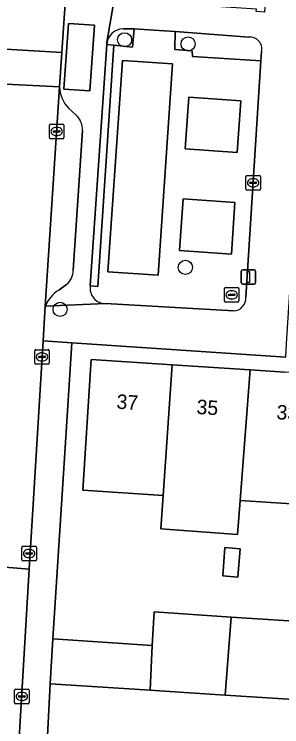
# Model space of a CAD drawing. Extents: x 160349 to 161355, y 381727 to 382854.
# Drawn here: x 160526.67 to 160545.13, y 382016.9 to 382066.09 of the extents above; entities that cross this region are included whole.
import ezdxf

# ---------------------------------------------------------------- set-up
doc = ezdxf.new("R2010")
doc.units = 0
for name, color, linetype in [('IMGEO_Boom', 7, 'Continuous'), ('IMGEO_Erf', 7, 'Continuous'), ('IMGEO_Groenvoorziening', 7, 'Continuous'), ('IMGEO_Haag', 7, 'Continuous'), ('IMGEO_Kolk', 7, 'Continuous'), ('IMGEO_Lichtmast', 7, 'Continuous'), ('IMGEO_Muur', 7, 'Continuous'), ('IMGEO_Pand', 7, 'Continuous'), ('IMGEO_Pand_nummerreeks', 7, 'Continuous'), ('IMGEO_Parkeervlak_open', 7, 'Continuous'), ('IMGEO_Rijbaan_lokaal_open', 7, 'Continuous'), ('IMGEO_Rioolput', 7, 'Continuous'), ('IMGEO_Terreindeel_open', 7, 'Continuous'), ('IMGEO_Voetpad_open', 7, 'Continuous')]:
    doc.layers.add(name, color=color, linetype=linetype)

msp = doc.modelspace()

# ---------------------------------------------------------------- linework, layer by layer
at = {"layer": 'IMGEO_Boom'}
for centre in [(160534.279, 382064.333), (160538.67, 382064.045), (160538.48, 382048.617), (160529.832, 382045.718)]:
    msp.add_circle(centre, 0.489, dxfattribs=at)
at = {"layer": 'IMGEO_Erf'}
for points in [[(160545.411, 382042.407), (160530.648, 382043.401), (160530.156, 382035.8), (160529.324, 382022.967), (160536.182, 382022.498), (160536.333, 382024.823), (160541.648, 382024.475), (160547.428, 382024.097)], [(160545.801, 382032.284), (160542.262, 382032.515), (160542.083, 382030.166), (160536.776, 382030.571), (160536.951, 382032.863), (160531.398, 382033.226), (160531.983, 382042.262), (160537.561, 382041.895), (160542.951, 382041.54), (160545.344, 382041.383)]]:
    msp.add_lwpolyline(points, dxfattribs=at)
msp.add_lwpolyline([(160541.057, 382027.312), (160541.206, 382029.27), (160542.259, 382029.19), (160542.11, 382027.231)], close=True, dxfattribs=at)
at = {"layer": 'IMGEO_Groenvoorziening'}
for points in [[(160533.05, 382064.002), (160533.532, 382063.953), (160534.836, 382063.824), (160534.948, 382065.084), (160534.185, 382065.082)], [(160542.854, 382064.514), (160537.786, 382064.905), (160537.741, 382063.667), (160538.946, 382063.573), (160538.961, 382063.186), (160543.699, 382062.877), (160543.741, 382063.523)]]:
    msp.add_lwpolyline(points, dxfattribs=at)
for points in [[(160531.913, 382047.338), (160532.438, 382047.299), (160533.532, 382063.953), (160533.05, 382064.002)], [(160536.594, 382048.071), (160537.601, 382062.665), (160534.129, 382062.904), (160533.122, 382048.311)]]:
    msp.add_lwpolyline(points, close=True, dxfattribs=at)
for centre, radius, start, end in [((160534.205, 382063.924), 1.158, 91.0047, 176.1505), ((160542.94, 382063.698), 0.82, 347.6775, 95.9832)]:
    msp.add_arc(centre, radius, start, end, dxfattribs=at)
at = {"layer": 'IMGEO_Haag'}
msp.add_lwpolyline([(160531.913, 382047.338), (160532.438, 382047.299), (160533.532, 382063.953), (160533.05, 382064.002)], close=True, dxfattribs=at)
at = {"layer": 'IMGEO_Kolk'}
for p, q in [((160529.094, 382057.573), (160529.094, 382058.425)), ((160529.169, 382058.499), (160530.021, 382058.499)), ((160530.095, 382058.425), (160530.095, 382057.573)), ((160529.353, 382057.993), (160529.353, 382058.005)), ((160529.791, 382057.956), (160529.393, 382057.956)), ((160529.396, 382058.042), (160529.794, 382058.042)), ((160529.582, 382058.279), (160529.607, 382058.279)), ((160529.837, 382058.005), (160529.837, 382057.993)), ((160530.021, 382057.499), (160529.169, 382057.499)), ((160529.605, 382057.719), (160529.58, 382057.719)), ((160542.658, 382054.03), (160542.658, 382054.882)), ((160542.733, 382054.956), (160543.585, 382054.956)), ((160543.659, 382054.882), (160543.659, 382054.03)), ((160542.917, 382054.45), (160542.917, 382054.462)), ((160543.355, 382054.413), (160542.957, 382054.413)), ((160542.96, 382054.499), (160543.358, 382054.499)), ((160543.146, 382054.736), (160543.171, 382054.736)), ((160543.401, 382054.462), (160543.401, 382054.45)), ((160543.585, 382053.956), (160542.733, 382053.956)), ((160543.169, 382054.176), (160543.144, 382054.176)), ((160528.08, 382042.008), (160528.08, 382042.86)), ((160528.155, 382042.934), (160529.007, 382042.934)), ((160528.568, 382042.714), (160528.593, 382042.714)), ((160529.081, 382042.86), (160529.081, 382042.008)), ((160528.339, 382042.428), (160528.339, 382042.44)), ((160528.777, 382042.391), (160528.379, 382042.391)), ((160528.382, 382042.477), (160528.78, 382042.477)), ((160528.591, 382042.154), (160528.566, 382042.154)), ((160528.823, 382042.44), (160528.823, 382042.428)), ((160529.007, 382041.934), (160528.155, 382041.934)), ((160527.269, 382029.359), (160528.121, 382029.359)), ((160527.194, 382028.433), (160527.194, 382029.285)), ((160527.453, 382028.853), (160527.453, 382028.865)), ((160527.891, 382028.816), (160527.493, 382028.816)), ((160527.496, 382028.902), (160527.894, 382028.902)), ((160527.682, 382029.139), (160527.707, 382029.139)), ((160527.937, 382028.865), (160527.937, 382028.853)), ((160528.195, 382029.285), (160528.195, 382028.433)), ((160528.121, 382028.359), (160527.269, 382028.359)), ((160527.705, 382028.579), (160527.68, 382028.579)), ((160526.763, 382019.491), (160527.615, 382019.491)), ((160526.688, 382018.565), (160526.688, 382019.417)), ((160526.947, 382018.985), (160526.947, 382018.997)), ((160526.99, 382019.034), (160527.388, 382019.034)), ((160527.176, 382019.271), (160527.201, 382019.271)), ((160527.431, 382018.997), (160527.431, 382018.985)), ((160527.689, 382019.417), (160527.689, 382018.565)), ((160527.615, 382018.491), (160526.763, 382018.491)), ((160527.385, 382018.948), (160526.987, 382018.948)), ((160527.199, 382018.711), (160527.174, 382018.711))]:
    msp.add_line(p, q, dxfattribs=at)
for points in [[(160529.094, 382057.573), (160529.094, 382058.425)], [(160529.169, 382058.499), (160530.021, 382058.499)], [(160530.095, 382058.425), (160530.095, 382057.573)], [(160530.021, 382057.499), (160529.169, 382057.499)], [(160542.658, 382054.03), (160542.658, 382054.882)], [(160542.733, 382054.956), (160543.585, 382054.956)], [(160543.659, 382054.882), (160543.659, 382054.03)], [(160543.585, 382053.956), (160542.733, 382053.956)], [(160528.08, 382042.008), (160528.08, 382042.86)], [(160528.155, 382042.934), (160529.007, 382042.934)], [(160529.081, 382042.86), (160529.081, 382042.008)], [(160529.007, 382041.934), (160528.155, 382041.934)], [(160527.269, 382029.359), (160528.121, 382029.359)], [(160527.194, 382028.433), (160527.194, 382029.285)], [(160528.195, 382029.285), (160528.195, 382028.433)], [(160528.121, 382028.359), (160527.269, 382028.359)], [(160526.763, 382019.491), (160527.615, 382019.491)], [(160526.688, 382018.565), (160526.688, 382019.417)], [(160527.689, 382019.417), (160527.689, 382018.565)], [(160527.615, 382018.491), (160526.763, 382018.491)]]:
    msp.add_lwpolyline(points, dxfattribs=at)
for centre, radius, start, end in [((160529.171, 382058.423), 0.0765, 91.552, 178.448), ((160529.171, 382058.423), 0.0765, 91.552, 178.448), ((160530.019, 382058.423), 0.0765, 1.552, 88.448), ((160530.019, 382058.423), 0.0765, 1.552, 88.448), ((160529.393, 382058.002), 0.0403, 85.8775, 175.7526), ((160529.39, 382057.992), 0.0366, 178.938, 274.7102), ((160529.794, 382057.999), 0.043, 264.8664, 352.4533), ((160529.798, 382058.004), 0.0386, 1.7309, 96.639), ((160529.171, 382057.575), 0.0765, 181.552, 268.448), ((160529.171, 382057.575), 0.0765, 181.552, 268.448), ((160530.019, 382057.575), 0.0765, 271.552, 358.448), ((160530.019, 382057.575), 0.0765, 271.552, 358.448), ((160542.735, 382054.88), 0.0765, 91.552, 178.448), ((160542.735, 382054.88), 0.0765, 91.552, 178.448), ((160543.583, 382054.88), 0.0765, 1.552, 88.448), ((160543.583, 382054.88), 0.0765, 1.552, 88.448), ((160542.957, 382054.459), 0.0403, 85.8775, 175.7526), ((160542.954, 382054.449), 0.0366, 178.938, 274.7102), ((160543.358, 382054.456), 0.043, 264.8664, 352.4533), ((160543.362, 382054.461), 0.0386, 1.7309, 96.639), ((160542.735, 382054.032), 0.0765, 181.552, 268.448), ((160542.735, 382054.032), 0.0765, 181.552, 268.448), ((160543.583, 382054.032), 0.0765, 271.552, 358.448), ((160543.583, 382054.032), 0.0765, 271.552, 358.448), ((160528.157, 382042.858), 0.0765, 91.552, 178.448), ((160528.157, 382042.858), 0.0765, 91.552, 178.448), ((160529.005, 382042.858), 0.0765, 1.552, 88.448), ((160529.005, 382042.858), 0.0765, 1.552, 88.448), ((160528.379, 382042.437), 0.0403, 85.8775, 175.7526), ((160528.376, 382042.427), 0.0366, 178.938, 274.7102), ((160528.78, 382042.434), 0.043, 264.8664, 352.4533), ((160528.784, 382042.439), 0.0386, 1.7309, 96.639), ((160528.157, 382042.01), 0.0765, 181.552, 268.448), ((160528.157, 382042.01), 0.0765, 181.552, 268.448), ((160529.005, 382042.01), 0.0765, 271.552, 358.448), ((160529.005, 382042.01), 0.0765, 271.552, 358.448), ((160527.271, 382029.283), 0.0765, 91.552, 178.448), ((160527.271, 382029.283), 0.0765, 91.552, 178.448), ((160528.119, 382029.283), 0.0765, 1.552, 88.448), ((160528.119, 382029.283), 0.0765, 1.552, 88.448), ((160527.493, 382028.862), 0.0403, 85.8775, 175.7526), ((160527.49, 382028.852), 0.0366, 178.938, 274.7102), ((160527.894, 382028.859), 0.043, 264.8664, 352.4533), ((160527.898, 382028.864), 0.0386, 1.7309, 96.639), ((160527.271, 382028.435), 0.0765, 181.552, 268.448), ((160527.271, 382028.435), 0.0765, 181.552, 268.448), ((160528.119, 382028.435), 0.0765, 271.552, 358.448), ((160528.119, 382028.435), 0.0765, 271.552, 358.448), ((160526.765, 382019.415), 0.0765, 91.552, 178.448), ((160526.765, 382019.415), 0.0765, 91.552, 178.448), ((160527.613, 382019.415), 0.0765, 1.552, 88.448), ((160527.613, 382019.415), 0.0765, 1.552, 88.448), ((160526.987, 382018.994), 0.0403, 85.8775, 175.7526), ((160526.984, 382018.984), 0.0366, 178.938, 274.7102), ((160527.388, 382018.991), 0.043, 264.8664, 352.4533), ((160527.392, 382018.996), 0.0386, 1.7309, 96.639), ((160526.765, 382018.567), 0.0765, 181.552, 268.448), ((160526.765, 382018.567), 0.0765, 181.552, 268.448), ((160527.613, 382018.567), 0.0765, 271.552, 358.448), ((160527.613, 382018.567), 0.0765, 271.552, 358.448)]:
    msp.add_arc(centre, radius, start, end, dxfattribs=at)
for centre, major_axis, ratio, start_param, end_param in [((160529.581, 382057.999), (-0.387, 0.002), 0.722429, 4.712389, 7.853982), ((160529.606, 382057.999), (-0.39, 0.002), 0.717154, 1.570796, 4.712389), ((160543.145, 382054.456), (-0.387, 0.002), 0.722429, 4.712389, 7.853982), ((160543.17, 382054.456), (-0.39, 0.002), 0.717154, 1.570796, 4.712389), ((160528.567, 382042.434), (-0.387, 0.002), 0.722429, 4.712389, 7.853982), ((160528.592, 382042.434), (-0.39, 0.002), 0.717154, 1.570796, 4.712389), ((160527.681, 382028.859), (-0.387, 0.002), 0.722429, 4.712389, 7.853982), ((160527.706, 382028.859), (-0.39, 0.002), 0.717154, 1.570796, 4.712389), ((160527.175, 382018.991), (-0.387, 0.002), 0.722429, 4.712389, 7.853982), ((160527.2, 382018.991), (-0.39, 0.002), 0.717154, 1.570796, 4.712389)]:
    msp.add_ellipse(centre, major_axis=major_axis, ratio=ratio, start_param=start_param, end_param=end_param, dxfattribs=at)
at = {"layer": 'IMGEO_Lichtmast'}
for p, q in [((160542.337, 382047.555), (160542.337, 382048.355)), ((160542.337, 382048.355), (160542.337, 382047.555)), ((160542.437, 382048.455), (160543.227, 382048.455)), ((160543.227, 382048.455), (160542.437, 382048.455)), ((160543.327, 382048.355), (160543.327, 382047.555)), ((160543.327, 382047.555), (160543.327, 382048.355)), ((160543.227, 382047.455), (160542.437, 382047.455)), ((160542.437, 382047.455), (160543.227, 382047.455))]:
    msp.add_line(p, q, dxfattribs=at)
msp.add_lwpolyline([(160542.757, 382048.33), (160542.907, 382048.33), (160542.907, 382047.58), (160542.757, 382047.58), (160542.757, 382048.33)], dxfattribs=at)
for centre, start, end in [((160542.437, 382048.355), 90, 180), ((160542.437, 382048.355), 90, 180), ((160543.227, 382048.355), 0, 90), ((160543.227, 382048.355), 360, 90), ((160542.437, 382047.555), 180, 270), ((160542.437, 382047.555), 180, 270), ((160543.227, 382047.555), 270, 0), ((160543.227, 382047.555), 270, 0)]:
    msp.add_arc(centre, 0.1, start, end, dxfattribs=at)
at = {"layer": 'IMGEO_Muur'}
msp.add_lwpolyline([(160530.156, 382035.8), (160529.324, 382022.967)], dxfattribs=at)
at = {"layer": 'IMGEO_Pand'}
for points in [[(160537.561, 382041.895), (160531.983, 382042.262), (160531.398, 382033.226), (160536.951, 382032.863)], [(160542.262, 382032.515), (160542.951, 382041.54), (160537.561, 382041.895), (160536.951, 382032.863), (160536.776, 382030.571), (160542.083, 382030.166)], [(160548.248, 382036.577), (160548.55, 382041.172), (160545.344, 382041.383), (160542.951, 382041.54), (160542.262, 382032.515), (160545.801, 382032.284), (160545.703, 382030.787), (160547.858, 382030.645), (160548.136, 382034.873)], [(160541.057, 382027.312), (160542.11, 382027.231), (160542.259, 382029.19), (160541.206, 382029.27)], [(160536.043, 382019.426), (160538.419, 382019.273), (160541.237, 382019.089), (160541.648, 382024.475), (160536.333, 382024.823), (160536.182, 382022.498)], [(160548.812, 382023.329), (160548.856, 382024.004), (160547.428, 382024.097), (160541.648, 382024.475), (160541.237, 382019.089), (160548.504, 382018.615), (160548.514, 382018.767)], [(160536.043, 382019.426), (160536.182, 382022.498), (160529.324, 382022.967), (160529.135, 382019.87)]]:
    msp.add_lwpolyline(points, close=True, dxfattribs=at)
at = {"layer": 'IMGEO_Parkeervlak_open'}
msp.add_lwpolyline([(160531.893, 382060.81), (160532.199, 382065.34), (160530.403, 382065.462), (160530.097, 382060.932)], close=True, dxfattribs=at)
for points in [[(160529.795, 382061.08), (160528.807, 382045.931)], [(160530.934, 382059.136), (160530.426, 382059.593)], [(160530.741, 382048.431), (160531.366, 382058.069)], [(160529.737, 382047.047), (160530.283, 382047.428)]]:
    msp.add_lwpolyline(points, dxfattribs=at)
for centre, radius, start, end in [((160531.964, 382061.123), 2.169, 181.1318, 224.8555), ((160530.053, 382058.159), 1.316, 356.0973, 47.9862), ((160529.365, 382048.453), 1.376, 311.8434, 359.0709), ((160530.915, 382045.12), 2.259, 121.4369, 158.952)]:
    msp.add_arc(centre, radius, start, end, dxfattribs=at)
at = {"layer": 'IMGEO_Rijbaan_lokaal_open'}
for points in [[(160525.275, 382063.726), (160529.962, 382063.456), (160530.734, 382074.953), (160526.048, 382075.185)], [(160525.134, 382061.313), (160529.795, 382061.08), (160529.962, 382063.456), (160525.275, 382063.726)], [(160528.807, 382045.931), (160529.795, 382061.08), (160525.134, 382061.313), (160522.929, 382028.173), (160527.69, 382027.78), (160528.002, 382032.642), (160528.662, 382043.535)]]:
    msp.add_lwpolyline(points, close=True, dxfattribs=at)
for points in [[(160552.548, 382034.524), (160549.547, 382034.761), (160549.494, 382034.035), (160548.856, 382024.004), (160548.812, 382023.329), (160553.839, 382023.002), (160553.543, 382018.441), (160548.514, 382018.767), (160548.504, 382018.615), (160541.237, 382019.089), (160538.419, 382019.273), (160536.043, 382019.426), (160529.135, 382019.87), (160528.873, 382014.469)], [(160526.719, 382011.433), (160527.69, 382027.78), (160522.929, 382028.173), (160522.836, 382027.224), (160521.895, 382012.476), (160521.512, 382011.289), (160519.525, 382006.044), (160514.813, 381996.196), (160514.455, 381995.447)]]:
    msp.add_lwpolyline(points, dxfattribs=at)
at = {"layer": 'IMGEO_Rioolput'}
for p, q in [((160541.174, 382046.295), (160541.174, 382047.147)), ((160541.249, 382047.221), (160542.101, 382047.221)), ((160542.175, 382047.147), (160542.175, 382046.295)), ((160541.433, 382046.715), (160541.433, 382046.727)), ((160541.871, 382046.678), (160541.473, 382046.678)), ((160541.476, 382046.764), (160541.874, 382046.764)), ((160541.662, 382047.001), (160541.687, 382047.001)), ((160541.917, 382046.727), (160541.917, 382046.715)), ((160542.101, 382046.221), (160541.249, 382046.221)), ((160541.685, 382046.441), (160541.66, 382046.441))]:
    msp.add_line(p, q, dxfattribs=at)
for points in [[(160541.174, 382046.295), (160541.174, 382047.147)], [(160541.249, 382047.221), (160542.101, 382047.221)], [(160542.175, 382047.147), (160542.175, 382046.295)], [(160542.101, 382046.221), (160541.249, 382046.221)]]:
    msp.add_lwpolyline(points, dxfattribs=at)
for centre, radius, start, end in [((160541.251, 382047.145), 0.0765, 91.552, 178.448), ((160541.251, 382047.145), 0.0765, 91.552, 178.448), ((160542.099, 382047.145), 0.0765, 1.552, 88.448), ((160542.099, 382047.145), 0.0765, 1.552, 88.448), ((160541.473, 382046.724), 0.0403, 85.8775, 175.7526), ((160541.47, 382046.714), 0.0366, 178.938, 274.7102), ((160541.874, 382046.721), 0.043, 264.8664, 352.4533), ((160541.878, 382046.726), 0.0386, 1.7309, 96.639), ((160541.251, 382046.297), 0.0765, 181.552, 268.448), ((160541.251, 382046.297), 0.0765, 181.552, 268.448), ((160542.099, 382046.297), 0.0765, 271.552, 358.448), ((160542.099, 382046.297), 0.0765, 271.552, 358.448)]:
    msp.add_arc(centre, radius, start, end, dxfattribs=at)
for centre, major_axis, ratio, start_param, end_param in [((160541.661, 382046.721), (-0.387, 0.002), 0.722429, 4.712389, 7.853982), ((160541.686, 382046.721), (-0.39, 0.002), 0.717154, 1.570796, 4.712389)]:
    msp.add_ellipse(centre, major_axis=major_axis, ratio=ratio, start_param=start_param, end_param=end_param, dxfattribs=at)
at = {"layer": 'IMGEO_Terreindeel_open'}
for points in [[(160542.06, 382056.543), (160542.306, 382060.115), (160538.721, 382060.362), (160538.475, 382056.79)], [(160541.658, 382049.533), (160541.904, 382053.099), (160538.319, 382053.346), (160538.073, 382049.78)]]:
    msp.add_lwpolyline(points, close=True, dxfattribs=at)
at = {"layer": 'IMGEO_Voetpad_open'}
for points in [[(160541.81, 382045.609), (160532.964, 382046.126), (160528.807, 382045.931), (160528.662, 382043.535), (160530.648, 382043.401), (160545.411, 382042.407), (160545.472, 382043.358), (160550.061, 382114.509)], [(160544.204, 382083.212), (160535.329, 382083.745), (160534.547, 382081.878), (160544.338, 382081.192), (160544.351, 382081.388), (160544.923, 382081.351), (160544.499, 382074.771), (160543.927, 382074.808), (160543.765, 382072.293), (160544.336, 382072.256), (160543.949, 382066.245), (160543.378, 382066.282), (160543.388, 382066.435), (160533.565, 382067.123), (160533.047, 382064.161), (160533.05, 382064.002)], [(160531, 382078.07), (160530.952, 382077.354), (160530.734, 382074.953), (160529.962, 382063.456), (160529.795, 382061.08)], [(160531.913, 382047.338), (160533.05, 382064.002), (160533.047, 382064.161), (160533.565, 382067.123), (160533.833, 382071.135)], [(160542.65, 382046.563), (160543.699, 382062.877), (160538.961, 382063.186), (160538.946, 382063.573), (160537.741, 382063.667), (160537.786, 382064.905), (160536.661, 382064.973), (160534.948, 382065.084), (160534.836, 382063.824), (160533.532, 382063.953), (160532.438, 382047.299), (160531.913, 382047.338)], [(160534.185, 382065.082), (160534.948, 382065.084), (160536.661, 382064.973), (160537.786, 382064.905), (160542.854, 382064.514)], [(160543.741, 382063.523), (160543.699, 382062.877), (160542.65, 382046.563)], [(160530.426, 382059.593), (160530.934, 382059.136)], [(160531.366, 382058.069), (160530.741, 382048.431)], [(160530.283, 382047.428), (160529.737, 382047.047)], [(160528.807, 382045.931), (160532.964, 382046.126)], [(160532.964, 382046.126), (160541.81, 382045.609)], [(160529.135, 382019.87), (160529.324, 382022.967), (160530.156, 382035.8), (160530.648, 382043.401), (160528.662, 382043.535), (160528.002, 382032.642), (160527.69, 382027.78), (160526.719, 382011.433)], [(160526.211, 382009.53), (160519.2, 381993.627), (160526.761, 381987.863), (160526.995, 381991.315), (160527.114, 381993.069), (160527.89, 382004.415), (160528.64, 382004.369), (160528.873, 382014.469), (160529.135, 382019.87)]]:
    msp.add_lwpolyline(points, dxfattribs=at)
for points in [[(160532.199, 382065.34), (160531.893, 382060.81), (160530.097, 382060.932), (160530.403, 382065.462)], [(160536.594, 382048.071), (160533.122, 382048.311), (160534.129, 382062.904), (160537.601, 382062.665)], [(160542.06, 382056.543), (160538.475, 382056.79), (160538.721, 382060.362), (160542.306, 382060.115)], [(160541.658, 382049.533), (160538.073, 382049.78), (160538.319, 382053.346), (160541.904, 382053.099)]]:
    msp.add_lwpolyline(points, close=True, dxfattribs=at)
for centre, radius, start, end in [((160534.205, 382063.924), 1.158, 91.0047, 176.1505), ((160542.94, 382063.698), 0.82, 347.6775, 95.9832), ((160531.964, 382061.123), 2.169, 181.1318, 224.8555), ((160530.053, 382058.159), 1.316, 356.0973, 47.9862), ((160529.365, 382048.453), 1.376, 311.8434, 359.0709), ((160530.915, 382045.12), 2.259, 121.4369, 158.952), ((160532.955, 382047.18), 1.054, 171.3618, 270.4994), ((160532.955, 382047.18), 1.054, 171.3618, 270.4994), ((160541.775, 382046.487), 0.878, 272.2878, 4.9842), ((160541.775, 382046.487), 0.878, 272.2878, 4.9842)]:
    msp.add_arc(centre, radius, start, end, dxfattribs=at)

# ---------------------------------------------------------------- texts
at = {"layer": 'IMGEO_Pand_nummerreeks'}
for s, p in [('37', (160533.705, 382038.863)), ('35', (160539.227, 382038.499)), ('33', (160544.749, 382038.136))]:
    msp.add_text(s, height=1, rotation=356.2357, dxfattribs=at).set_placement(p)

doc.saveas('drawing.dxf')
